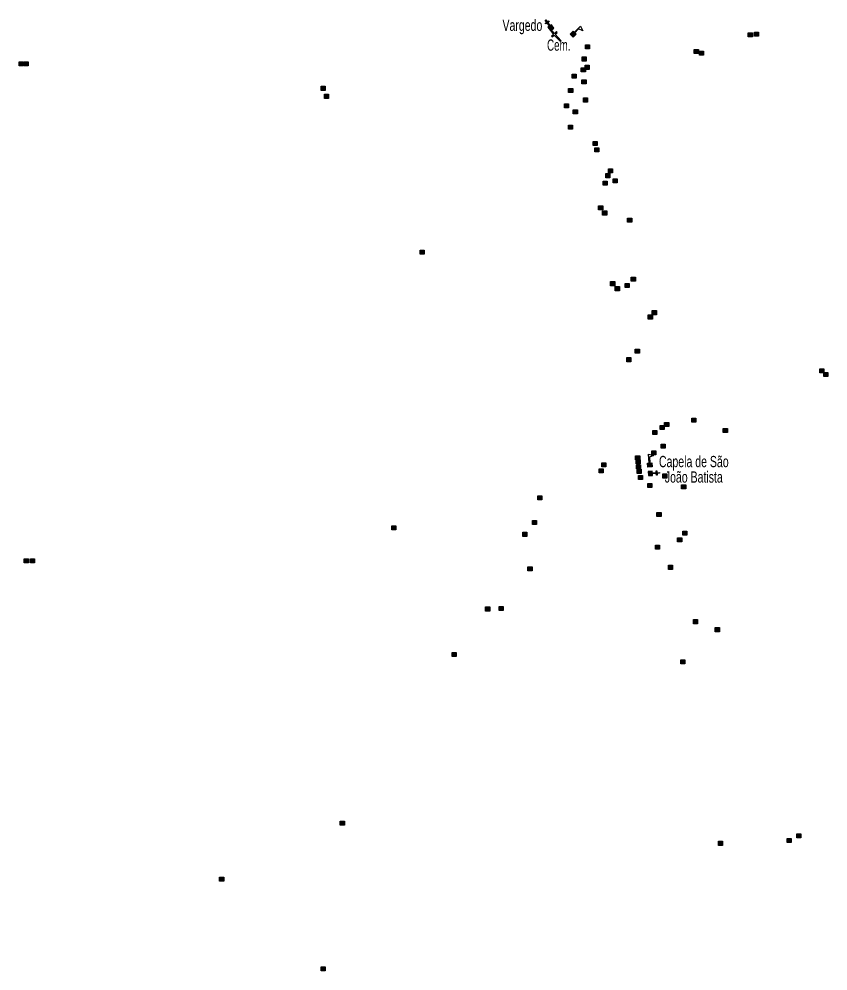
# Model space of a CAD drawing. Extents: x 647.8 to 672.9, y 6929.3 to 6957.3.
# Drawn here: x 666.28 to 672.03, y 6943.34 to 6950.11 of the extents above; entities that cross this region are included whole.
import ezdxf
from ezdxf.enums import TextEntityAlignment as Align

# ---------------------------------------------------------------- set-up
doc = ezdxf.new("R2010")
doc.units = 0
doc.header["$LTSCALE"] = 0.032
for name, color, linetype, lineweight in [('2', 7, 'Continuous', 25), ('20', 7, 'Continuous', 25), ('4', 7, 'Continuous', 25), ('6', 7, 'Continuous', 25)]:
    doc.layers.add(name, color=color, linetype=linetype, lineweight=lineweight)
doc.layers.add('61', color=7, linetype='Continuous')

msp = doc.modelspace()

# ---------------------------------------------------------------- hatches: boundary and pattern name
at = {"layer": '2'}
for points in [[(671.4627, 6950.008), (671.4917, 6950.008), (671.4917, 6949.979), (671.4627, 6949.979)], [(671.5066, 6950.0124), (671.5356, 6950.0124), (671.5356, 6949.9834), (671.5066, 6949.9834)], [(670.3044, 6949.9224), (670.3334, 6949.9224), (670.3334, 6949.8934), (670.3044, 6949.8934)], [(670.2824, 6949.8369), (670.3114, 6949.8369), (670.3114, 6949.8079), (670.2824, 6949.8079)], [(671.0788, 6949.8895), (671.1078, 6949.8895), (671.1078, 6949.8605), (671.0788, 6949.8605)], [(671.1161, 6949.8785), (671.1451, 6949.8785), (671.1451, 6949.8495), (671.1161, 6949.8495)], [(666.2787, 6949.8018), (666.3077, 6949.8018), (666.3077, 6949.7728), (666.2787, 6949.7728)], [(666.3138, 6949.8018), (666.3428, 6949.8018), (666.3428, 6949.7728), (666.3138, 6949.7728)], [(670.2758, 6949.7601), (670.3048, 6949.7601), (670.3048, 6949.7311), (670.2758, 6949.7311)], [(670.3022, 6949.7776), (670.3312, 6949.7776), (670.3312, 6949.7486), (670.3022, 6949.7486)], [(670.21, 6949.714), (670.239, 6949.714), (670.239, 6949.685), (670.21, 6949.685)], [(668.4264, 6949.6284), (668.4554, 6949.6284), (668.4554, 6949.5994), (668.4264, 6949.5994)], [(670.2802, 6949.6745), (670.3092, 6949.6745), (670.3092, 6949.6455), (670.2802, 6949.6455)], [(668.4506, 6949.5714), (668.4796, 6949.5714), (668.4796, 6949.5424), (668.4506, 6949.5424)], [(670.1859, 6949.6131), (670.2149, 6949.6131), (670.2149, 6949.5841), (670.1859, 6949.5841)], [(670.1552, 6949.5034), (670.1842, 6949.5034), (670.1842, 6949.4744), (670.1552, 6949.4744)], [(670.2912, 6949.5451), (670.3202, 6949.5451), (670.3202, 6949.5161), (670.2912, 6949.5161)], [(670.2188, 6949.4617), (670.2478, 6949.4617), (670.2478, 6949.4327), (670.2188, 6949.4327)], [(670.1837, 6949.352), (670.2127, 6949.352), (670.2127, 6949.323), (670.1837, 6949.323)], [(670.3592, 6949.2357), (670.3882, 6949.2357), (670.3882, 6949.2067), (670.3592, 6949.2067)], [(670.3724, 6949.1919), (670.4014, 6949.1919), (670.4014, 6949.1629), (670.3724, 6949.1629)], [(670.4689, 6949.0427), (670.4979, 6949.0427), (670.4979, 6949.0137), (670.4689, 6949.0137)], [(670.4316, 6948.9549), (670.4606, 6948.9549), (670.4606, 6948.9259), (670.4316, 6948.9259)], [(670.4492, 6949.0076), (670.4782, 6949.0076), (670.4782, 6948.9786), (670.4492, 6948.9786)], [(670.5018, 6948.9703), (670.5308, 6948.9703), (670.5308, 6948.9413), (670.5018, 6948.9413)], [(670.3987, 6948.7794), (670.4277, 6948.7794), (670.4277, 6948.7504), (670.3987, 6948.7504)], [(670.4272, 6948.7421), (670.4562, 6948.7421), (670.4562, 6948.7131), (670.4272, 6948.7131)], [(670.6049, 6948.6917), (670.6339, 6948.6917), (670.6339, 6948.6627), (670.6049, 6948.6627)], [(669.1307, 6948.4635), (669.1597, 6948.4635), (669.1597, 6948.4345), (669.1307, 6948.4345)], [(670.6312, 6948.2726), (670.6602, 6948.2726), (670.6602, 6948.2436), (670.6312, 6948.2436)], [(670.4843, 6948.2397), (670.5133, 6948.2397), (670.5133, 6948.2107), (670.4843, 6948.2107)], [(670.5172, 6948.2046), (670.5462, 6948.2046), (670.5462, 6948.1756), (670.5172, 6948.1756)], [(670.5874, 6948.2266), (670.6164, 6948.2266), (670.6164, 6948.1976), (670.5874, 6948.1976)], [(670.7519, 6948.0028), (670.7809, 6948.0028), (670.7809, 6947.9738), (670.7519, 6947.9738)], [(670.7804, 6948.0335), (670.8094, 6948.0335), (670.8094, 6948.0045), (670.7804, 6948.0045)], [(670.6598, 6947.7593), (670.6888, 6947.7593), (670.6888, 6947.7303), (670.6598, 6947.7303)], [(670.5983, 6947.7), (670.6273, 6947.7), (670.6273, 6947.671), (670.5983, 6947.671)], [(671.9717, 6947.6211), (672.0007, 6947.6211), (672.0007, 6947.5921), (671.9717, 6947.5921)], [(672.0002, 6947.5947), (672.0292, 6947.5947), (672.0292, 6947.5657), (672.0002, 6947.5657)], [(671.0612, 6947.2701), (671.0902, 6947.2701), (671.0902, 6947.2411), (671.0612, 6947.2411)], [(670.8353, 6947.2174), (670.8643, 6947.2174), (670.8643, 6947.1884), (670.8353, 6947.1884)], [(670.8682, 6947.2393), (670.8972, 6947.2393), (670.8972, 6947.2103), (670.8682, 6947.2103)], [(671.285, 6947.1955), (671.314, 6947.1955), (671.314, 6947.1665), (671.285, 6947.1665)], [(670.7848, 6947.1823), (670.8138, 6947.1823), (670.8138, 6947.1533), (670.7848, 6947.1533)], [(670.844, 6947.0858), (670.873, 6947.0858), (670.873, 6947.0568), (670.844, 6947.0568)], [(670.662, 6947.0024), (670.691, 6947.0024), (670.691, 6946.9734), (670.662, 6946.9734)], [(670.776, 6947.0375), (670.805, 6947.0375), (670.805, 6947.0085), (670.776, 6947.0085)], [(670.4206, 6946.9519), (670.4496, 6946.9519), (670.4496, 6946.9229), (670.4206, 6946.9229)], [(670.6663, 6946.9739), (670.6953, 6946.9739), (670.6953, 6946.9449), (670.6663, 6946.9449)], [(670.6685, 6946.9388), (670.6975, 6946.9388), (670.6975, 6946.9098), (670.6685, 6946.9098)], [(670.4031, 6946.9103), (670.4321, 6946.9103), (670.4321, 6946.8813), (670.4031, 6946.8813)], [(670.6729, 6946.9059), (670.7019, 6946.9059), (670.7019, 6946.8769), (670.6729, 6946.8769)], [(670.6817, 6946.862), (670.7107, 6946.862), (670.7107, 6946.833), (670.6817, 6946.833)], [(670.8546, 6946.873), (670.8836, 6946.873), (670.8836, 6946.844), (670.8546, 6946.844)], [(670.7492, 6946.8047), (670.7782, 6946.8047), (670.7782, 6946.7757), (670.7492, 6946.7757)], [(670.9888, 6946.7962), (671.0178, 6946.7962), (671.0178, 6946.7672), (670.9888, 6946.7672)], [(669.9665, 6946.7172), (669.9955, 6946.7172), (669.9955, 6946.6882), (669.9665, 6946.6882)], [(670.8133, 6946.5987), (670.8423, 6946.5987), (670.8423, 6946.5697), (670.8133, 6946.5697)], [(669.9292, 6946.5417), (669.9582, 6946.5417), (669.9582, 6946.5127), (669.9292, 6946.5127)], [(668.9288, 6946.5044), (668.9578, 6946.5044), (668.9578, 6946.4754), (668.9288, 6946.4754)], [(669.859, 6946.4583), (669.888, 6946.4583), (669.888, 6946.4293), (669.859, 6946.4293)], [(670.9976, 6946.4671), (671.0266, 6946.4671), (671.0266, 6946.4381), (670.9976, 6946.4381)], [(670.9603, 6946.4188), (670.9893, 6946.4188), (670.9893, 6946.3898), (670.9603, 6946.3898)], [(670.8024, 6946.3662), (670.8314, 6946.3662), (670.8314, 6946.3372), (670.8024, 6946.3372)], [(666.3159, 6946.2697), (666.3449, 6946.2697), (666.3449, 6946.2407), (666.3159, 6946.2407)], [(666.3598, 6946.2697), (666.3888, 6946.2697), (666.3888, 6946.2407), (666.3598, 6946.2407)], [(669.8963, 6946.2126), (669.9253, 6946.2126), (669.9253, 6946.1836), (669.8963, 6946.1836)], [(670.8945, 6946.2236), (670.9235, 6946.2236), (670.9235, 6946.1946), (670.8945, 6946.1946)], [(669.5957, 6945.9274), (669.6247, 6945.9274), (669.6247, 6945.8984), (669.5957, 6945.8984)], [(669.6923, 6945.9318), (669.7213, 6945.9318), (669.7213, 6945.9028), (669.6923, 6945.9028)], [(671.0722, 6945.8375), (671.1012, 6945.8375), (671.1012, 6945.8085), (671.0722, 6945.8085)], [(671.228, 6945.7804), (671.257, 6945.7804), (671.257, 6945.7514), (671.228, 6945.7514)], [(669.3566, 6945.6049), (669.3856, 6945.6049), (669.3856, 6945.5759), (669.3566, 6945.5759)], [(670.9823, 6945.5523), (671.0113, 6945.5523), (671.0113, 6945.5233), (670.9823, 6945.5233)], [(668.5624, 6944.4049), (668.5914, 6944.4049), (668.5914, 6944.3759), (668.5624, 6944.3759)], [(671.7391, 6944.282), (671.7681, 6944.282), (671.7681, 6944.253), (671.7391, 6944.253)], [(671.8071, 6944.3149), (671.8361, 6944.3149), (671.8361, 6944.2859), (671.8071, 6944.2859)], [(671.2499, 6944.2623), (671.2789, 6944.2623), (671.2789, 6944.2333), (671.2499, 6944.2333)], [(667.7047, 6944.0078), (667.7337, 6944.0078), (667.7337, 6943.9788), (667.7047, 6943.9788)], [(668.4264, 6943.3694), (668.4554, 6943.3694), (668.4554, 6943.3404), (668.4264, 6943.3404)]]:
    msp.add_hatch(color=256, dxfattribs=at).paths.add_polyline_path(points)
at = {"layer": '4'}
for points in [[(670.1961, 6949.9984), (670.2168, 6950.0201), (670.2385, 6949.9993), (670.2178, 6949.9777)], [(670.749, 6946.9203), (670.7464, 6946.9502), (670.7763, 6946.9528), (670.7789, 6946.9229)]]:
    msp.add_hatch(color=256, dxfattribs=at).paths.add_polyline_path(points)
at = {"layer": '6'}
for points in [[(670.0529, 6950.0589), (670.0488, 6950.0561), (670.0329, 6950.0785), (670.0227, 6950.0713), (670.0198, 6950.0754), (670.0301, 6950.0826), (670.0199, 6950.0969), (670.024, 6950.0998), (670.0341, 6950.0855), (670.0443, 6950.0927), (670.0472, 6950.0886), (670.037, 6950.0814)], [(670.0386, 6950.0488), (670.056, 6950.0244), (670.0804, 6950.0417), (670.0631, 6950.0662)], [(670.7806, 6946.8925), (670.7506, 6946.8908), (670.7523, 6946.8609), (670.7822, 6946.8625)], [(670.7815, 6946.875), (670.7812, 6946.88), (670.8087, 6946.8815), (670.808, 6946.894), (670.813, 6946.8943), (670.8137, 6946.8818), (670.8312, 6946.8828), (670.8314, 6946.8778), (670.814, 6946.8768), (670.8147, 6946.8643), (670.8097, 6946.864), (670.809, 6946.8765)]]:
    msp.add_hatch(color=256, dxfattribs=at).paths.add_polyline_path(points)

# ---------------------------------------------------------------- linework, layer by layer
at = {"layer": '2'}
for points in [[(671.4627, 6950.008), (671.4917, 6950.008), (671.4917, 6949.979), (671.4627, 6949.979)], [(671.5066, 6950.0124), (671.5356, 6950.0124), (671.5356, 6949.9834), (671.5066, 6949.9834)], [(670.3044, 6949.9224), (670.3334, 6949.9224), (670.3334, 6949.8934), (670.3044, 6949.8934)], [(670.2824, 6949.8369), (670.3114, 6949.8369), (670.3114, 6949.8079), (670.2824, 6949.8079)], [(671.0788, 6949.8895), (671.1078, 6949.8895), (671.1078, 6949.8605), (671.0788, 6949.8605)], [(671.1161, 6949.8785), (671.1451, 6949.8785), (671.1451, 6949.8495), (671.1161, 6949.8495)], [(666.2787, 6949.8018), (666.3077, 6949.8018), (666.3077, 6949.7728), (666.2787, 6949.7728)], [(666.3138, 6949.8018), (666.3428, 6949.8018), (666.3428, 6949.7728), (666.3138, 6949.7728)], [(670.2758, 6949.7601), (670.3048, 6949.7601), (670.3048, 6949.7311), (670.2758, 6949.7311)], [(670.3022, 6949.7776), (670.3312, 6949.7776), (670.3312, 6949.7486), (670.3022, 6949.7486)], [(670.21, 6949.714), (670.239, 6949.714), (670.239, 6949.685), (670.21, 6949.685)], [(668.4264, 6949.6284), (668.4554, 6949.6284), (668.4554, 6949.5994), (668.4264, 6949.5994)], [(670.2802, 6949.6745), (670.3092, 6949.6745), (670.3092, 6949.6455), (670.2802, 6949.6455)], [(668.4506, 6949.5714), (668.4796, 6949.5714), (668.4796, 6949.5424), (668.4506, 6949.5424)], [(670.1859, 6949.6131), (670.2149, 6949.6131), (670.2149, 6949.5841), (670.1859, 6949.5841)], [(670.1552, 6949.5034), (670.1842, 6949.5034), (670.1842, 6949.4744), (670.1552, 6949.4744)], [(670.2912, 6949.5451), (670.3202, 6949.5451), (670.3202, 6949.5161), (670.2912, 6949.5161)], [(670.2188, 6949.4617), (670.2478, 6949.4617), (670.2478, 6949.4327), (670.2188, 6949.4327)], [(670.1837, 6949.352), (670.2127, 6949.352), (670.2127, 6949.323), (670.1837, 6949.323)], [(670.3592, 6949.2357), (670.3882, 6949.2357), (670.3882, 6949.2067), (670.3592, 6949.2067)], [(670.3724, 6949.1919), (670.4014, 6949.1919), (670.4014, 6949.1629), (670.3724, 6949.1629)], [(670.4689, 6949.0427), (670.4979, 6949.0427), (670.4979, 6949.0137), (670.4689, 6949.0137)], [(670.4316, 6948.9549), (670.4606, 6948.9549), (670.4606, 6948.9259), (670.4316, 6948.9259)], [(670.4492, 6949.0076), (670.4782, 6949.0076), (670.4782, 6948.9786), (670.4492, 6948.9786)], [(670.5018, 6948.9703), (670.5308, 6948.9703), (670.5308, 6948.9413), (670.5018, 6948.9413)], [(670.3987, 6948.7794), (670.4277, 6948.7794), (670.4277, 6948.7504), (670.3987, 6948.7504)], [(670.4272, 6948.7421), (670.4562, 6948.7421), (670.4562, 6948.7131), (670.4272, 6948.7131)], [(670.6049, 6948.6917), (670.6339, 6948.6917), (670.6339, 6948.6627), (670.6049, 6948.6627)], [(669.1307, 6948.4635), (669.1597, 6948.4635), (669.1597, 6948.4345), (669.1307, 6948.4345)], [(670.6312, 6948.2726), (670.6602, 6948.2726), (670.6602, 6948.2436), (670.6312, 6948.2436)], [(670.4843, 6948.2397), (670.5133, 6948.2397), (670.5133, 6948.2107), (670.4843, 6948.2107)], [(670.5172, 6948.2046), (670.5462, 6948.2046), (670.5462, 6948.1756), (670.5172, 6948.1756)], [(670.5874, 6948.2266), (670.6164, 6948.2266), (670.6164, 6948.1976), (670.5874, 6948.1976)], [(670.7519, 6948.0028), (670.7809, 6948.0028), (670.7809, 6947.9738), (670.7519, 6947.9738)], [(670.7804, 6948.0335), (670.8094, 6948.0335), (670.8094, 6948.0045), (670.7804, 6948.0045)], [(670.6598, 6947.7593), (670.6888, 6947.7593), (670.6888, 6947.7303), (670.6598, 6947.7303)], [(670.5983, 6947.7), (670.6273, 6947.7), (670.6273, 6947.671), (670.5983, 6947.671)], [(671.9717, 6947.6211), (672.0007, 6947.6211), (672.0007, 6947.5921), (671.9717, 6947.5921)], [(672.0002, 6947.5947), (672.0292, 6947.5947), (672.0292, 6947.5657), (672.0002, 6947.5657)], [(671.0612, 6947.2701), (671.0902, 6947.2701), (671.0902, 6947.2411), (671.0612, 6947.2411)], [(670.8353, 6947.2174), (670.8643, 6947.2174), (670.8643, 6947.1884), (670.8353, 6947.1884)], [(670.8682, 6947.2393), (670.8972, 6947.2393), (670.8972, 6947.2103), (670.8682, 6947.2103)], [(671.285, 6947.1955), (671.314, 6947.1955), (671.314, 6947.1665), (671.285, 6947.1665)], [(670.7848, 6947.1823), (670.8138, 6947.1823), (670.8138, 6947.1533), (670.7848, 6947.1533)], [(670.844, 6947.0858), (670.873, 6947.0858), (670.873, 6947.0568), (670.844, 6947.0568)], [(670.662, 6947.0024), (670.691, 6947.0024), (670.691, 6946.9734), (670.662, 6946.9734)], [(670.776, 6947.0375), (670.805, 6947.0375), (670.805, 6947.0085), (670.776, 6947.0085)], [(670.4206, 6946.9519), (670.4496, 6946.9519), (670.4496, 6946.9229), (670.4206, 6946.9229)], [(670.6663, 6946.9739), (670.6953, 6946.9739), (670.6953, 6946.9449), (670.6663, 6946.9449)], [(670.6685, 6946.9388), (670.6975, 6946.9388), (670.6975, 6946.9098), (670.6685, 6946.9098)], [(670.4031, 6946.9103), (670.4321, 6946.9103), (670.4321, 6946.8813), (670.4031, 6946.8813)], [(670.6729, 6946.9059), (670.7019, 6946.9059), (670.7019, 6946.8769), (670.6729, 6946.8769)], [(670.6817, 6946.862), (670.7107, 6946.862), (670.7107, 6946.833), (670.6817, 6946.833)], [(670.8546, 6946.873), (670.8836, 6946.873), (670.8836, 6946.844), (670.8546, 6946.844)], [(670.7492, 6946.8047), (670.7782, 6946.8047), (670.7782, 6946.7757), (670.7492, 6946.7757)], [(670.9888, 6946.7962), (671.0178, 6946.7962), (671.0178, 6946.7672), (670.9888, 6946.7672)], [(669.9665, 6946.7172), (669.9955, 6946.7172), (669.9955, 6946.6882), (669.9665, 6946.6882)], [(670.8133, 6946.5987), (670.8423, 6946.5987), (670.8423, 6946.5697), (670.8133, 6946.5697)], [(669.9292, 6946.5417), (669.9582, 6946.5417), (669.9582, 6946.5127), (669.9292, 6946.5127)], [(668.9288, 6946.5044), (668.9578, 6946.5044), (668.9578, 6946.4754), (668.9288, 6946.4754)], [(669.859, 6946.4583), (669.888, 6946.4583), (669.888, 6946.4293), (669.859, 6946.4293)], [(670.9976, 6946.4671), (671.0266, 6946.4671), (671.0266, 6946.4381), (670.9976, 6946.4381)], [(670.9603, 6946.4188), (670.9893, 6946.4188), (670.9893, 6946.3898), (670.9603, 6946.3898)], [(670.8024, 6946.3662), (670.8314, 6946.3662), (670.8314, 6946.3372), (670.8024, 6946.3372)], [(666.3159, 6946.2697), (666.3449, 6946.2697), (666.3449, 6946.2407), (666.3159, 6946.2407)], [(666.3598, 6946.2697), (666.3888, 6946.2697), (666.3888, 6946.2407), (666.3598, 6946.2407)], [(669.8963, 6946.2126), (669.9253, 6946.2126), (669.9253, 6946.1836), (669.8963, 6946.1836)], [(670.8945, 6946.2236), (670.9235, 6946.2236), (670.9235, 6946.1946), (670.8945, 6946.1946)], [(669.5957, 6945.9274), (669.6247, 6945.9274), (669.6247, 6945.8984), (669.5957, 6945.8984)], [(669.6923, 6945.9318), (669.7213, 6945.9318), (669.7213, 6945.9028), (669.6923, 6945.9028)], [(671.0722, 6945.8375), (671.1012, 6945.8375), (671.1012, 6945.8085), (671.0722, 6945.8085)], [(671.228, 6945.7804), (671.257, 6945.7804), (671.257, 6945.7514), (671.228, 6945.7514)], [(669.3566, 6945.6049), (669.3856, 6945.6049), (669.3856, 6945.5759), (669.3566, 6945.5759)], [(670.9823, 6945.5523), (671.0113, 6945.5523), (671.0113, 6945.5233), (670.9823, 6945.5233)], [(668.5624, 6944.4049), (668.5914, 6944.4049), (668.5914, 6944.3759), (668.5624, 6944.3759)], [(671.7391, 6944.282), (671.7681, 6944.282), (671.7681, 6944.253), (671.7391, 6944.253)], [(671.8071, 6944.3149), (671.8361, 6944.3149), (671.8361, 6944.2859), (671.8071, 6944.2859)], [(671.2499, 6944.2623), (671.2789, 6944.2623), (671.2789, 6944.2333), (671.2499, 6944.2333)], [(667.7047, 6944.0078), (667.7337, 6944.0078), (667.7337, 6943.9788), (667.7047, 6943.9788)], [(668.4264, 6943.3694), (668.4554, 6943.3694), (668.4554, 6943.3404), (668.4264, 6943.3404)]]:
    msp.add_lwpolyline(points, close=True, dxfattribs=at)
at = {"layer": '20'}
for points in [[(670.0842, 6950.0045), (670.0653, 6950.0252), (670.0594, 6950.0198), (670.0783, 6949.9991)], [(670.0783, 6949.9991), (670.0635, 6949.9856), (670.0692, 6949.9793), (670.084, 6949.9928), (670.1269, 6949.946)], [(670.0899, 6949.9982), (670.1047, 6950.0117), (670.0989, 6950.018), (670.0842, 6950.0045)], [(670.1269, 6949.946), (670.1328, 6949.9514), (670.0899, 6949.9982)]]:
    msp.add_lwpolyline(points, dxfattribs=at)
at = {"layer": '4'}
for p, q in [((670.2259, 6950.0114), (670.2295, 6950.008)), ((670.7589, 6946.9513), (670.7639, 6946.9517))]:
    msp.add_line(p, q, dxfattribs=at)
for points in [[(670.2259, 6950.0114), (670.2691, 6950.0566), (670.2857, 6950.0234), (670.2568, 6950.0365), (670.2295, 6950.008)], [(670.1961, 6949.9984), (670.2168, 6950.0201), (670.2385, 6949.9993), (670.2178, 6949.9777)], [(670.7589, 6946.9513), (670.7535, 6947.0135), (670.7894, 6947.0041), (670.7604, 6946.9911), (670.7639, 6946.9517)], [(670.749, 6946.9203), (670.7464, 6946.9502), (670.7763, 6946.9528), (670.7789, 6946.9229)]]:
    msp.add_lwpolyline(points, close=True, dxfattribs=at)
at = {"layer": '6'}
for points in [[(670.0529, 6950.0589), (670.0488, 6950.0561), (670.0329, 6950.0785), (670.0227, 6950.0713), (670.0198, 6950.0754), (670.0301, 6950.0826), (670.0199, 6950.0969), (670.024, 6950.0998), (670.0341, 6950.0855), (670.0443, 6950.0927), (670.0472, 6950.0886), (670.037, 6950.0814)], [(670.0386, 6950.0488), (670.056, 6950.0244), (670.0804, 6950.0417), (670.0631, 6950.0662)], [(670.7806, 6946.8925), (670.7506, 6946.8908), (670.7523, 6946.8609), (670.7822, 6946.8625)], [(670.7815, 6946.875), (670.7812, 6946.88), (670.8087, 6946.8815), (670.808, 6946.894), (670.813, 6946.8943), (670.8137, 6946.8818), (670.8312, 6946.8828), (670.8314, 6946.8778), (670.814, 6946.8768), (670.8147, 6946.8643), (670.8097, 6946.864), (670.809, 6946.8765)]]:
    msp.add_lwpolyline(points, close=True, dxfattribs=at)

# ---------------------------------------------------------------- texts
at = {"layer": '61', "width": 0.7}
msp.add_text('        Vargedo  ', height=0.08, dxfattribs=at).set_placement((670.0401, 6950.022), align=Align.RIGHT)
at = {"layer": '61'}
for s, width, p in [('Cem.', 0.65, (670.0321, 6949.8811)), ('Capela de São', 0.7, (670.8278, 6946.9211)), ('  João Batista', 0.7, (670.8278, 6946.8111))]:
    msp.add_text(s, height=0.08, dxfattribs=dict(at, width=width)).set_placement(p)

doc.saveas('drawing.dxf')
